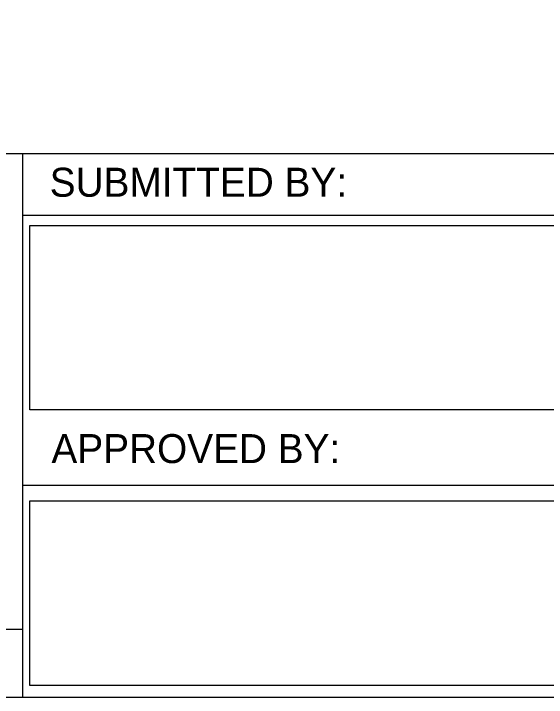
# Model space of a CAD drawing. Extents: x 0 to 1270, y 0 to 830.
# Drawn here: x 650.9 to 709.7, y 0 to 75.5 of the extents above; entities that cross this region are included whole.
import ezdxf

# ---------------------------------------------------------------- set-up
doc = ezdxf.new("R2010")
doc.units = 0
for name, color, linetype in [('CT_Border_Perimeter_Shape', 7, 'Continuous'), ('CT_DigSig_Field1', 7, 'Continuous'), ('CT_DigSig_Field2', 7, 'Continuous'), ('CT_Signature_Field_CTDOT', 7, 'Continuous'), ('CT_Title_Block_Linework', 7, 'Continuous'), ('CT_Title_Block_Text', 7, 'Continuous')]:
    doc.layers.add(name, color=color, linetype=linetype)

# ---------------------------------------------------------------- blocks, each defined once
blk = doc.blocks.new('Digital_Signature_State_Design')
at = {"layer": 'CT_DigSig_Field1'}
blk.add_lwpolyline([(652.67, 21.675), (801.151, 21.675), (801.151, 1.318), (652.67, 1.318)], close=True, dxfattribs=at)
blk = doc.blocks.new('BDR_CTDOT_Standards')
at = {"layer": 'CT_Border_Perimeter_Shape'}
blk.add_lwpolyline([(0, 0), (1270, 0), (1270, 830), (0, 830)], close=True, dxfattribs=at)
at = {"layer": 'CT_Signature_Field_CTDOT'}
for p, q in [((651.861, 53.22), (802.516, 53.22)), ((651.861, 23.428), (802.516, 23.428))]:
    blk.add_line(p, q, dxfattribs=at)
at = {"layer": 'CT_Title_Block_Linework'}
for p, q in [((1270, 60), (0, 60)), ((651.861, 60), (651.861, 0)), ((651.861, 7.5), (435.948, 7.5))]:
    blk.add_line(p, q, dxfattribs=at)
at = {"layer": 'CT_DigSig_Field1'}
blk.add_blockref('Digital_Signature_State_Design', (0, 30.414), dxfattribs=at)
at = {"layer": 'CT_DigSig_Field2'}
blk.add_blockref('Digital_Signature_State_Design', (0, 0), dxfattribs=at)
at = {"layer": 'CT_Signature_Field_CTDOT'}
blk.add_text('APPROVED BY:  ', height=3.2, dxfattribs=at).set_placement((655.066, 25.853))
at = {"layer": 'CT_Title_Block_Text'}
blk.add_text('SUBMITTED BY:', height=3.2, dxfattribs=at).set_placement((654.876, 55.251))

msp = doc.modelspace()

# ---------------------------------------------------------------- block references
at = {"layer": 'CT_Title_Block_Text'}
msp.add_blockref('BDR_CTDOT_Standards', (0, 0), dxfattribs=at)

doc.saveas('drawing.dxf')
